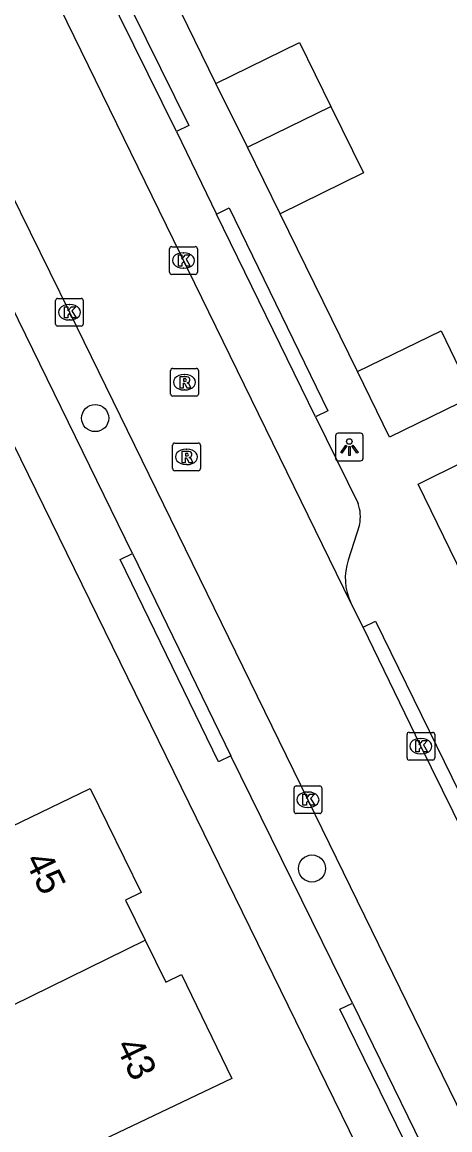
# Model space of a CAD drawing. Extents: x 160457 to 162082, y 388340 to 389736.
# Drawn here: x 160899.08 to 160914.53, y 388812.73 to 388852.76 of the extents above; entities that cross this region are included whole.
import ezdxf

# ---------------------------------------------------------------- set-up
doc = ezdxf.new("R2010")
doc.units = 0
for name, color, linetype in [('IMGEO_Boom', 7, 'Continuous'), ('IMGEO_Kolk', 7, 'Continuous'), ('IMGEO_Lichtpunt', 7, 'Continuous'), ('IMGEO_Pand', 7, 'Continuous'), ('IMGEO_Pand_nummerreeks', 7, 'Continuous'), ('IMGEO_Rijbaan_lokaal_gesloten', 7, 'Continuous'), ('IMGEO_Rioolput', 7, 'Continuous'), ('IMGEO_Voetpad_open', 7, 'Continuous')]:
    doc.layers.add(name, color=color, linetype=linetype)

msp = doc.modelspace()

# ---------------------------------------------------------------- linework, layer by layer
at = {"layer": 'IMGEO_Boom'}
for centre in [(160901.715, 388838.45), (160909.551, 388822.172)]:
    msp.add_circle(centre, 0.489, dxfattribs=at)
at = {"layer": 'IMGEO_Kolk'}
for p, q in [((160904.407, 388843.72), (160904.407, 388844.572)), ((160904.482, 388844.646), (160905.334, 388844.646)), ((160904.895, 388844.426), (160904.92, 388844.426)), ((160905.408, 388844.572), (160905.408, 388843.72)), ((160905.334, 388843.646), (160904.482, 388843.646)), ((160904.918, 388843.866), (160904.893, 388843.866)), ((160900.36, 388842.776), (160901.212, 388842.776)), ((160900.285, 388841.85), (160900.285, 388842.702)), ((160900.773, 388842.556), (160900.798, 388842.556)), ((160901.286, 388842.702), (160901.286, 388841.85)), ((160900.796, 388841.996), (160900.771, 388841.996)), ((160901.212, 388841.776), (160900.36, 388841.776)), ((160912.985, 388826.167), (160912.985, 388827.019)), ((160913.06, 388827.093), (160913.912, 388827.093)), ((160913.473, 388826.873), (160913.498, 388826.873)), ((160913.986, 388827.019), (160913.986, 388826.167)), ((160913.912, 388826.093), (160913.06, 388826.093)), ((160913.496, 388826.313), (160913.471, 388826.313)), ((160908.978, 388825.156), (160909.83, 388825.156)), ((160908.903, 388824.23), (160908.903, 388825.082)), ((160909.391, 388824.936), (160909.416, 388824.936)), ((160909.904, 388825.082), (160909.904, 388824.23)), ((160909.414, 388824.376), (160909.389, 388824.376)), ((160909.83, 388824.156), (160908.978, 388824.156))]:
    msp.add_line(p, q, dxfattribs=at)
for points in [[(160904.407, 388843.72), (160904.407, 388844.572)], [(160904.482, 388844.646), (160905.334, 388844.646)], [(160905.408, 388844.572), (160905.408, 388843.72)], [(160904.728, 388844.346), (160904.851, 388844.346), (160904.851, 388844.195), (160904.981, 388844.346), (160905.145, 388844.346), (160904.999, 388844.195), (160905.152, 388843.946), (160905, 388843.946), (160904.915, 388844.11), (160904.851, 388844.043), (160904.851, 388843.946), (160904.728, 388843.946), (160904.728, 388844.346)], [(160905.334, 388843.646), (160904.482, 388843.646)], [(160900.36, 388842.776), (160901.212, 388842.776)], [(160900.285, 388841.85), (160900.285, 388842.702)], [(160900.606, 388842.476), (160900.729, 388842.476), (160900.729, 388842.325), (160900.859, 388842.476), (160901.023, 388842.476), (160900.877, 388842.325), (160901.03, 388842.076), (160900.878, 388842.076), (160900.793, 388842.24), (160900.729, 388842.173), (160900.729, 388842.076), (160900.606, 388842.076), (160900.606, 388842.476)], [(160901.286, 388842.702), (160901.286, 388841.85)], [(160901.212, 388841.776), (160900.36, 388841.776)], [(160912.985, 388826.167), (160912.985, 388827.019)], [(160913.06, 388827.093), (160913.912, 388827.093)], [(160913.306, 388826.793), (160913.429, 388826.793), (160913.429, 388826.642), (160913.559, 388826.793), (160913.723, 388826.793), (160913.577, 388826.642), (160913.73, 388826.393), (160913.578, 388826.393), (160913.493, 388826.557), (160913.429, 388826.49), (160913.429, 388826.393), (160913.306, 388826.393), (160913.306, 388826.793)], [(160913.986, 388827.019), (160913.986, 388826.167)], [(160913.912, 388826.093), (160913.06, 388826.093)], [(160908.978, 388825.156), (160909.83, 388825.156)], [(160908.903, 388824.23), (160908.903, 388825.082)], [(160909.224, 388824.856), (160909.347, 388824.856), (160909.347, 388824.705), (160909.477, 388824.856), (160909.641, 388824.856), (160909.495, 388824.705), (160909.648, 388824.456), (160909.496, 388824.456), (160909.411, 388824.62), (160909.347, 388824.553), (160909.347, 388824.456), (160909.224, 388824.456), (160909.224, 388824.856)], [(160909.904, 388825.082), (160909.904, 388824.23)], [(160909.83, 388824.156), (160908.978, 388824.156)]]:
    msp.add_lwpolyline(points, dxfattribs=at)
for centre, start, end in [((160904.484, 388844.57), 91.552, 178.448), ((160904.484, 388844.57), 91.552, 178.448), ((160905.332, 388844.57), 1.552, 88.448), ((160905.332, 388844.57), 1.552, 88.448), ((160904.484, 388843.722), 181.552, 268.448), ((160904.484, 388843.722), 181.552, 268.448), ((160905.332, 388843.722), 271.552, 358.448), ((160905.332, 388843.722), 271.552, 358.448), ((160900.362, 388842.7), 91.552, 178.448), ((160900.362, 388842.7), 91.552, 178.448), ((160901.21, 388842.7), 1.552, 88.448), ((160901.21, 388842.7), 1.552, 88.448), ((160900.362, 388841.852), 181.552, 268.448), ((160900.362, 388841.852), 181.552, 268.448), ((160901.21, 388841.852), 271.552, 358.448), ((160901.21, 388841.852), 271.552, 358.448), ((160913.062, 388827.017), 91.552, 178.448), ((160913.062, 388827.017), 91.552, 178.448), ((160913.91, 388827.017), 1.552, 88.448), ((160913.91, 388827.017), 1.552, 88.448), ((160913.062, 388826.169), 181.552, 268.448), ((160913.062, 388826.169), 181.552, 268.448), ((160913.91, 388826.169), 271.552, 358.448), ((160913.91, 388826.169), 271.552, 358.448), ((160908.98, 388825.08), 91.552, 178.448), ((160908.98, 388825.08), 91.552, 178.448), ((160909.828, 388825.08), 1.552, 88.448), ((160909.828, 388825.08), 1.552, 88.448), ((160908.98, 388824.232), 181.552, 268.448), ((160908.98, 388824.232), 181.552, 268.448), ((160909.828, 388824.232), 271.552, 358.448), ((160909.828, 388824.232), 271.552, 358.448)]:
    msp.add_arc(centre, 0.0765, start, end, dxfattribs=at)
for centre, major_axis, ratio, start_param, end_param in [((160904.894, 388844.146), (-0.387, 0.002), 0.722429, 4.712389, 7.853982), ((160904.919, 388844.146), (-0.39, 0.002), 0.717154, 1.570796, 4.712389), ((160900.772, 388842.276), (-0.387, 0.002), 0.722429, 4.712389, 7.853982), ((160900.797, 388842.276), (-0.39, 0.002), 0.717154, 1.570796, 4.712389), ((160913.472, 388826.593), (-0.387, 0.002), 0.722429, 4.712389, 7.853982), ((160913.497, 388826.593), (-0.39, 0.002), 0.717154, 1.570796, 4.712389), ((160909.39, 388824.656), (-0.387, 0.002), 0.722429, 4.712389, 7.853982), ((160909.415, 388824.656), (-0.39, 0.002), 0.717154, 1.570796, 4.712389)]:
    msp.add_ellipse(centre, major_axis=major_axis, ratio=ratio, start_param=start_param, end_param=end_param, dxfattribs=at)
at = {"layer": 'IMGEO_Lichtpunt'}
for p, q in [((160910.403, 388837.807), (160910.403, 388837)), ((160910.403, 388837.807), (160910.403, 388837)), ((160911.305, 388837.902), (160910.497, 388837.902)), ((160911.305, 388837.902), (160910.497, 388837.902)), ((160911.399, 388837), (160911.399, 388837.807)), ((160911.399, 388837), (160911.399, 388837.807)), ((160910.497, 388836.906), (160911.305, 388836.906)), ((160910.497, 388836.906), (160911.305, 388836.906))]:
    msp.add_line(p, q, dxfattribs=at)
for points in [[(160910.777, 388837.471), (160910.816, 388837.443), (160910.628, 388837.181), (160910.59, 388837.208), (160910.777, 388837.471)], [(160910.879, 388837.423), (160910.926, 388837.423), (160910.926, 388837.101), (160910.879, 388837.101), (160910.879, 388837.423)], [(160910.989, 388837.443), (160911.027, 388837.47), (160911.214, 388837.208), (160911.175, 388837.18), (160910.989, 388837.443)]]:
    msp.add_lwpolyline(points, dxfattribs=at)
msp.add_circle((160910.902, 388837.605), 0.0994, dxfattribs=at)
for centre, start, end in [((160910.497, 388837.807), 90, 180), ((160910.497, 388837.807), 90, 180), ((160911.305, 388837.807), 0, 90), ((160911.305, 388837.807), 0, 90), ((160910.497, 388837), 180, 270), ((160910.497, 388837), 180, 270), ((160911.305, 388837), 270, 0), ((160911.305, 388837), 270, 360)]:
    msp.add_arc(centre, 0.0946, start, end, dxfattribs=at)
at = {"layer": 'IMGEO_Pand'}
for points in [[(160906.082, 388850.549), (160909.098, 388852.03), (160910.233, 388849.718)], [(160907.217, 388848.238), (160906.082, 388850.549)], [(160907.217, 388848.238), (160910.233, 388849.718)], [(160910.233, 388849.718), (160911.416, 388847.309), (160908.4, 388845.828)], [(160908.4, 388845.828), (160907.217, 388848.238)], [(160911.194, 388840.13), (160914.215, 388841.6), (160915.367, 388839.233)], [(160915.367, 388839.233), (160912.346, 388837.762), (160911.194, 388840.13)], [(160895.536, 388825.644), (160896.909, 388822.836), (160901.534, 388825.059), (160903.379, 388821.304), (160902.814, 388821.026), (160903.519, 388819.584)], [(160894.605, 388815.207), (160903.519, 388819.584)], [(160903.519, 388819.584), (160904.264, 388818.059), (160904.83, 388818.335), (160906.657, 388814.588), (160902.033, 388812.378), (160903.406, 388809.569)]]:
    msp.add_lwpolyline(points, dxfattribs=at)
at = {"layer": 'IMGEO_Rijbaan_lokaal_gesloten'}
for points in [[(160910.956, 388831.772), (160896.329, 388861.695), (160887.06, 388880.61), (160885.899, 388882.993)], [(160882.647, 388879.267), (160885.54, 388873.4), (160892.253, 388859.641), (160900.787, 388842.277), (160909.404, 388824.657), (160917.312, 388808.452), (160924.513, 388793.746), (160925.346, 388792.037)], [(160911.402, 388830.898), (160910.956, 388831.772)], [(160915.819, 388821.851), (160913.485, 388826.593), (160911.402, 388830.898)]]:
    msp.add_lwpolyline(points, dxfattribs=at)
at = {"layer": 'IMGEO_Rioolput'}
for p, q in [((160904.444, 388839.321), (160904.444, 388840.173)), ((160904.519, 388840.247), (160905.371, 388840.247)), ((160904.932, 388840.027), (160904.957, 388840.027)), ((160905.445, 388840.173), (160905.445, 388839.321)), ((160905.371, 388839.247), (160904.519, 388839.247)), ((160904.955, 388839.467), (160904.93, 388839.467)), ((160904.516, 388836.623), (160904.516, 388837.475)), ((160904.591, 388837.549), (160905.443, 388837.549)), ((160905.004, 388837.329), (160905.029, 388837.329)), ((160905.517, 388837.475), (160905.517, 388836.623)), ((160905.027, 388836.769), (160905.002, 388836.769)), ((160905.443, 388836.549), (160904.591, 388836.549))]:
    msp.add_line(p, q, dxfattribs=at)
for points in [[(160904.444, 388839.321), (160904.444, 388840.173)], [(160904.519, 388840.247), (160905.371, 388840.247)], [(160905.445, 388840.173), (160905.445, 388839.321)], [(160905.033, 388839.945), (160904.781, 388839.947), (160904.781, 388839.547)], [(160904.781, 388839.547), (160904.905, 388839.547), (160904.905, 388839.709), (160904.916, 388839.709)], [(160904.959, 388839.866), (160904.905, 388839.866), (160904.905, 388839.785)], [(160904.905, 388839.785), (160904.957, 388839.785)], [(160904.963, 388839.68), (160905.034, 388839.547), (160905.174, 388839.547), (160905.109, 388839.673)], [(160905.371, 388839.247), (160904.519, 388839.247)], [(160904.516, 388836.623), (160904.516, 388837.475)], [(160904.591, 388837.549), (160905.443, 388837.549)], [(160905.105, 388837.247), (160904.853, 388837.249), (160904.853, 388836.849)], [(160905.031, 388837.168), (160904.977, 388837.168), (160904.977, 388837.087)], [(160905.517, 388837.475), (160905.517, 388836.623)], [(160904.853, 388836.849), (160904.977, 388836.849), (160904.977, 388837.011), (160904.988, 388837.011)], [(160904.977, 388837.087), (160905.029, 388837.087)], [(160905.035, 388836.982), (160905.106, 388836.849), (160905.246, 388836.849), (160905.181, 388836.975)], [(160905.443, 388836.549), (160904.591, 388836.549)]]:
    msp.add_lwpolyline(points, dxfattribs=at)
for centre, radius, start, end in [((160904.521, 388840.171), 0.0765, 91.552, 178.448), ((160904.521, 388840.171), 0.0765, 91.552, 178.448), ((160905.369, 388840.171), 0.0765, 1.552, 88.448), ((160905.369, 388840.171), 0.0765, 1.552, 88.448), ((160904.915, 388839.656), 0.0533, 26.0293, 88.6989), ((160904.941, 388839.974), 0.19, 274.7715, 282.9687), ((160904.965, 388839.77), 0.0964, 77.0061, 93.1865), ((160904.979, 388839.827), 0.0378, 276.6634, 79.6772), ((160905.032, 388839.835), 0.109, 350.3612, 89.416), ((160905.03, 388839.835), 0.112, 277.5842, 350.9817), ((160905.014, 388839.62), 0.108, 29.5134, 73.7905), ((160904.521, 388839.323), 0.0765, 181.552, 268.448), ((160904.521, 388839.323), 0.0765, 181.552, 268.448), ((160905.369, 388839.323), 0.0765, 271.552, 358.448), ((160905.369, 388839.323), 0.0765, 271.552, 358.448), ((160904.593, 388837.473), 0.0765, 91.552, 178.448), ((160904.593, 388837.473), 0.0765, 91.552, 178.448), ((160905.037, 388837.072), 0.0964, 77.0061, 93.1865), ((160905.051, 388837.129), 0.0378, 276.6634, 79.6772), ((160905.104, 388837.137), 0.109, 350.3612, 89.416), ((160905.441, 388837.473), 0.0765, 1.552, 88.448), ((160905.441, 388837.473), 0.0765, 1.552, 88.448), ((160904.987, 388836.958), 0.0533, 26.0293, 88.6989), ((160905.013, 388837.276), 0.19, 274.7715, 282.9687), ((160905.102, 388837.137), 0.112, 277.5842, 350.9817), ((160905.086, 388836.922), 0.108, 29.5134, 73.7905), ((160904.593, 388836.625), 0.0765, 181.552, 268.448), ((160904.593, 388836.625), 0.0765, 181.552, 268.448), ((160905.441, 388836.625), 0.0765, 271.552, 358.448), ((160905.441, 388836.625), 0.0765, 271.552, 358.448)]:
    msp.add_arc(centre, radius, start, end, dxfattribs=at)
for centre, major_axis, ratio, start_param, end_param in [((160904.931, 388839.747), (-0.387, 0.002), 0.722429, 4.712389, 7.853982), ((160904.956, 388839.747), (-0.39, 0.002), 0.717154, 1.570796, 4.712389), ((160905.003, 388837.049), (-0.387, 0.002), 0.722429, 4.712389, 7.853982), ((160905.028, 388837.049), (-0.39, 0.002), 0.717154, 1.570796, 4.712389)]:
    msp.add_ellipse(centre, major_axis=major_axis, ratio=ratio, start_param=start_param, end_param=end_param, dxfattribs=at)
at = {"layer": 'IMGEO_Voetpad_open'}
for points in [[(160923.043, 388787.867), (160881.086, 388873.64), (160879.017, 388877.835)], [(160901.054, 388856.106), (160901.502, 388856.327), (160905.103, 388849.024), (160904.655, 388848.803)], [(160904.655, 388848.803), (160901.054, 388856.106)], [(160906.082, 388850.549), (160903.289, 388856.251)], [(160904.655, 388848.803), (160906.104, 388845.826)], [(160906.104, 388845.826), (160906.554, 388846.044), (160910.121, 388838.712), (160909.672, 388838.494)], [(160909.672, 388838.494), (160906.104, 388845.826)], [(160911.194, 388840.13), (160908.4, 388845.828)], [(160903.069, 388833.562), (160898.697, 388842.502)], [(160915.008, 388832.729), (160913.382, 388836.064), (160921.836, 388840.253)], [(160909.672, 388838.494), (160911.215, 388835.363)], [(160911.269, 388834.598), (160910.858, 388833.32)], [(160906.62, 388826.241), (160906.171, 388826.023), (160902.62, 388833.344), (160903.069, 388833.562)], [(160903.069, 388833.562), (160906.62, 388826.241)], [(160911.402, 388830.898), (160911.851, 388831.117), (160916.268, 388822.07), (160915.819, 388821.851)], [(160911.01, 388817.301), (160906.62, 388826.241)], [(160914.506, 388810.154), (160914.057, 388809.935), (160910.561, 388817.082), (160911.01, 388817.301)], [(160911.01, 388817.301), (160914.506, 388810.154)]]:
    msp.add_lwpolyline(points, dxfattribs=at)
for centre, radius, start, end in [((160909.939, 388834.889), 1.362, 347.6805, 20.3949), ((160912.843, 388832.669), 2.089, 161.8333, 205.4115)]:
    msp.add_arc(centre, radius, start, end, dxfattribs=at)

# ---------------------------------------------------------------- texts
at = {"layer": 'IMGEO_Pand_nummerreeks'}
for s, rotation, p in [('45', 296.1668, (160899.149, 388822.477)), ('43', 295.9934, (160902.434, 388815.767))]:
    msp.add_text(s, height=1, rotation=rotation, dxfattribs=at).set_placement(p)

doc.saveas('drawing.dxf')
